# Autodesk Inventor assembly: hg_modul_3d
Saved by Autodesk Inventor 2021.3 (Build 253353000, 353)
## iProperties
Created: 2024-04
Part Number: hg_modul_3d
Document SubType Name: Assembly
Designer: AdminForWorker
Title: hg_modul_3d v12
Author: AdminForWorker
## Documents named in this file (3)
- c:\worker\convert-fusion-r01-cosv3\tmp\job-1\2034\temp\files\9a142961-273b-48e5-bd82-d39b28c1852d\49558756-bad7-4411-824b-d0062a583a8e.iam
- c:\worker\convert-fusion-r01-cosv3\tmp\job-1\2034\temp\files\9a142961-273b-48e5-bd82-d39b28c1852d\modul_3d v1.iam
- c:\worker\convert-fusion-r01-cosv3\tmp\job-1\2034\temp\files\9a142961-273b-48e5-bd82-d39b28c1852d\OSSD-128x64 v1.ipt
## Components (2 placed, 2 different names)
1. modul_3d v1:1 [sub-assembly]
2. OSSD-128x64 v1:1
